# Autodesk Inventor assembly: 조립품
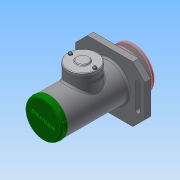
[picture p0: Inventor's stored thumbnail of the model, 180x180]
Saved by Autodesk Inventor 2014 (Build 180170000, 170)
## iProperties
Created: 2017-10
Part Number: 조립품
Document SubType Name: Assembly
Designer: net
Author: net
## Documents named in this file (20)
- C:\Users\net\Desktop\471007V1013\조립품.iam
- C:\Users\net\Desktop\471007V1013\본체.ipt
- C:\Users\net\Desktop\471007V1013\사이드 커버.ipt
- 사이드 커버.ipt
- C:\Users\net\Desktop\471007V1013\축.ipt
- C:\Users\net\Desktop\471007V1013\베어링 15 x 35 x 11.ipt
- C:\Users\net\Desktop\471007V1013\부시1.ipt
- C:\Users\net\Desktop\471007V1013\부시2.ipt
- C:\Users\net\Desktop\471007V1013\멈춤링 15 x 1.ipt
- C:\Users\net\Desktop\471007V1013\멈춤링 35x1.6.ipt
- C:\Users\net\Desktop\471007V1013\너트 M10.ipt
- C:\Users\net\Desktop\471007V1013\오일 실 15 25 7.ipt
- C:\Users\net\Desktop\471007V1013\와셔 10x21.ipt
- C:\Users\net\Desktop\471007V1013\V-벨트풀리.ipt
- C:\Users\net\Desktop\471007V1013\볼트 M4 x 10.ipt
- C:\Users\net\Desktop\471007V1013\와셔 4x16.ipt
- C:\Users\net\Desktop\471007V1013\키 4 x 4 x 18.ipt
- C:\Users\net\Desktop\471007V1013\십자볼트 M3 x 10.ipt
- C:\Users\net\Desktop\471007V1013\와셔 3x6.ipt
- C:\Users\net\Desktop\471007V1013\탑 커버.ipt
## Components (2 placed, 2 different names)
1. V-벨트풀리:1
2. ISO 4017 M4 x 10:1
